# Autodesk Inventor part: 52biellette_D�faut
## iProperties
Created: 2011-01
Part Number: 52biellette_D�faut
Document SubType Name: Modeling
Designer: eric
Density: 1 g/cm^3
Mass: 2.95797 g
Surface Area: 35.1572 cm^2
Volume: 2.95797 cm^3
Author: eric
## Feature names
1. Base1
